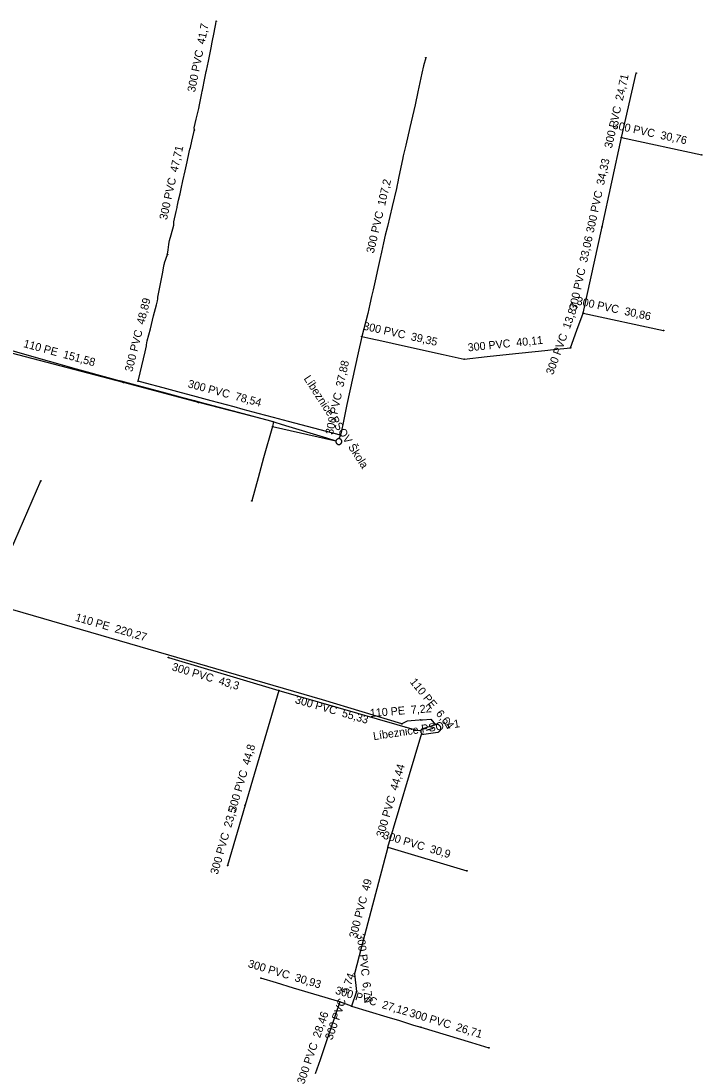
# Model space of a CAD drawing. Extents: x -736536 to -735428, y -1032997 to -1031649.
# Drawn here: x -735684.2 to -735428.6, y -1032358.4 to -1031967 of the extents above; entities that cross this region are included whole.
import ezdxf

# ---------------------------------------------------------------- set-up
doc = ezdxf.new("R2010")
doc.units = 0
for name, color, linetype in [('Vrstva 1', 7, 'Continuous'), ('Vrstva 20', 7, 'Continuous'), ('Vrstva 26', 7, 'Continuous'), ('Vrstva 29', 7, 'Continuous'), ('Vrstva 63', 7, 'Continuous')]:
    doc.layers.add(name, color=color, linetype=linetype)

# ---------------------------------------------------------------- blocks, each defined once
blk = doc.blocks.new('100')
at = {"layer": 'Vrstva 1'}
blk.add_circle((0, 0), 0.127, dxfattribs=at)

msp = doc.modelspace()

# ---------------------------------------------------------------- linework, layer by layer
at = {"layer": 'Vrstva 20'}
for p, q in [((-735458.86, -1032010.73), (-735453.32, -1031986.65)), ((-735466.16, -1032044.27), (-735458.86, -1032010.73)), ((-735458.86, -1032010.73), (-735428.79, -1032017.22)), ((-735473.28, -1032076.55), (-735466.16, -1032044.27)), ((-735473.28, -1032076.55), (-735443.12, -1032083.07)), ((-735645.66, -1032102.59), (-735715.244, -1032084.381)), ((-735617.54, -1032110.05), (-735645.66, -1032102.59)), ((-735589.45, -1032117.35), (-735617.54, -1032110.05)), ((-735589.45, -1032117.35), (-735589.74, -1032119.01)), ((-735589.74, -1032119.01), (-735565.962, -1032124.454)), ((-735564.26, -1032122.35), (-735564.87, -1032123.71)), ((-735698.803, -1032190.303), (-735676.675, -1032139.454)), ((-735628.82, -1032205.61), (-735587.37, -1032217.978)), ((-735587.37, -1032217.978), (-735600.075, -1032260.977)), ((-735600.075, -1032260.977), (-735606.6, -1032283.564)), ((-735546.475, -1032276.767), (-735516.898, -1032285.582)), ((-735559.05, -1032324.13), (-735558.24, -1032330.84)), ((-735558.24, -1032330.84), (-735560.13, -1032336.26)), ((-735560.13, -1032336.26), (-735564.49, -1032334.7))]:
    msp.add_line(p, q, dxfattribs=at)
for points in [[(-735619.095, -1032007.99), (-735619.03, -1032007.69), (-735619.18, -1032007.08), (-735618.392, -1032003.904), (-735617.51, -1032000.35), (-735617.39, -1031999.91), (-735617.127, -1031998.504), (-735616.299, -1031994.07), (-735616.18, -1031993.43), (-735616.09, -1031993.04), (-735615.191, -1031988.559), (-735614.67, -1031985.96), (-735614.52, -1031985.62), (-735613.807, -1031982.084), (-735612.813, -1031977.158), (-735612.378, -1031974.993), (-735611.67, -1031971.354), (-735611.42, -1031970.07), (-735611.05, -1031968.166), (-735610.86, -1031967.19)], [(-735532.28, -1031980.85), (-735533.13, -1031983.85), (-735533.735, -1031986.653), (-735535.246, -1031993.65), (-735536.298, -1031998.522), (-735538.256, -1032007.008), (-735539.784, -1032013.608), (-735540.726, -1032017.675), (-735541.03, -1032018.99), (-735542.368, -1032025.376), (-735542.914, -1032028.022), (-735543, -1032028.44), (-735543.325, -1032029.814), (-735544.917, -1032036.554), (-735546.686, -1032044.042), (-735547.47, -1032047.36), (-735548.108, -1032050.234), (-735548.876, -1032053.69), (-735549.485, -1032056.417), (-735550.248, -1032059.817), (-735551.28, -1032064.403), (-735552.049, -1032067.836), (-735552.583, -1032070.316), (-735553.22, -1032073.17), (-735554.05, -1032076.675), (-735556.31, -1032085.31)], [(-735629.165, -1032054.543), (-735629.159, -1032054.506), (-735628.907, -1032052.814), (-735628.614, -1032050.852), (-735628.49, -1032050.02), (-735628.44, -1032049.41), (-735627.817, -1032047.174), (-735626.821, -1032043.596), (-735626.73, -1032043.27), (-735626.83, -1032042.41), (-735625.93, -1032038.5), (-735625.589, -1032037.015), (-735625.5, -1032036.63), (-735625.44, -1032036.06), (-735625.019, -1032034.215), (-735624.469, -1032031.799), (-735624.055, -1032029.983), (-735623.399, -1032026.979), (-735622.559, -1032023.228), (-735621.818, -1032019.923), (-735620.987, -1032016.211), (-735620.74, -1032015.11), (-735620.58, -1032014.5), (-735620.021, -1032012.057), (-735619.303, -1032008.916), (-735619.16, -1032008.29), (-735619.095, -1032007.99)], [(-735640.14, -1032102.1), (-735639.387, -1032098.888), (-735637.564, -1032091.121), (-735637.02, -1032088.8), (-735637.09, -1032088.41), (-735636.737, -1032087.005), (-735635.587, -1032082.434), (-735634.369, -1032077.588), (-735633.332, -1032073.463), (-735632.951, -1032071.948), (-735632.75, -1032071.15), (-735632.76, -1032070.58), (-735632.269, -1032068.051), (-735630.939, -1032061.202), (-735630.622, -1032059.565), (-735630.38, -1032058.32), (-735630.32, -1032058.005), (-735630.26, -1032057.69), (-735629.17, -1032054.58), (-735629.165, -1032054.543)], [(-735478.02, -1032089.58), (-735475.62, -1032082.983), (-735473.28, -1032076.55)], [(-735711.93, -1032083.64), (-735710.215, -1032084.147), (-735706.827, -1032085.147), (-735703.84, -1032086.03), (-735701.86, -1032086.591), (-735696.429, -1032088.129), (-735687.14, -1032090.76), (-735673.546, -1032094.61), (-735670.44, -1032095.49), (-735663.396, -1032097.408), (-735648.81, -1032101.381), (-735646.72, -1032101.95), (-735642.593, -1032103.055), (-735629.88, -1032106.459), (-735624.464, -1032107.91), (-735619.062, -1032109.356), (-735616.92, -1032109.93), (-735602.71, -1032113.7), (-735590.5, -1032116.94), (-735584.952, -1032118.64), (-735569.541, -1032123.361), (-735566.41, -1032124.32), (-735565.957, -1032124.433)], [(-735556.31, -1032085.31), (-735557.667, -1032091.471), (-735561.93, -1032110.83), (-735563.196, -1032117.088), (-735564.042, -1032121.273), (-735564.26, -1032122.35)], [(-735556.31, -1032085.31), (-735552.942, -1032086.058), (-735548.826, -1032086.972), (-735541.067, -1032088.695), (-735525.707, -1032092.106), (-735517.9, -1032093.84)], [(-735517.9, -1032093.84), (-735509.211, -1032092.834), (-735500.966, -1032091.967), (-735487.583, -1032090.601), (-735484.342, -1032090.248), (-735478.02, -1032089.58)], [(-735564.26, -1032122.35), (-735569.543, -1032120.944), (-735583.791, -1032117.153), (-735589.462, -1032115.644), (-735595.094, -1032114.145), (-735600.75, -1032112.64), (-735604.144, -1032111.735), (-735612.776, -1032109.424), (-735619.63, -1032107.59), (-735623.875, -1032106.453), (-735630.726, -1032104.62), (-735637.394, -1032102.835), (-735640.14, -1032102.1)], [(-735589.74, -1032119.01), (-735593.12, -1032130.83), (-735595.161, -1032138.3), (-735597.53, -1032146.97)], [(-735541.28, -1032230.47), (-735571.062, -1032221.558), (-735694.194, -1032185.738), (-735696.415, -1032191.131), (-735716.431, -1032239.875), (-735718.846, -1032239.806)], [(-735587.37, -1032217.978), (-735535.76, -1032232.887), (-735534.549, -1032232.97), (-735534.151, -1032232.997)], [(-735534.316, -1032229.048), (-735534.797, -1032229.103), (-735539.26, -1032229.46), (-735541.28, -1032230.47)], [(-735534.316, -1032229.048), (-735533.52, -1032228.957), (-735530.441, -1032228.709), (-735528.7, -1032230.836)], [(-735546.475, -1032276.767), (-735534.149, -1032235.217), (-735533.799, -1032234.169)], [(-735529.544, -1032232.225), (-735529.624, -1032232.247), (-735531.755, -1032232.838), (-735532.134, -1032232.944)], [(-735546.475, -1032276.767), (-735556.378, -1032314.067), (-735559.05, -1032324.13)], [(-735564.49, -1032334.7), (-735581.866, -1032329.504), (-735588.265, -1032327.591), (-735594.12, -1032325.84)], [(-735564.49, -1032334.7), (-735569.907, -1032350.464), (-735571.96, -1032356.44), (-735573.74, -1032361.62)], [(-735560.13, -1032336.26), (-735546.868, -1032340.309), (-735542.172, -1032341.743), (-735536.85, -1032343.368), (-735534.19, -1032344.18)], [(-735534.19, -1032344.18), (-735515.14, -1032349.971), (-735508.63, -1032351.95)]]:
    msp.add_lwpolyline(points, dxfattribs=at)
at = {"layer": 'Vrstva 26'}
for points in [[(-735565.44, -1032123.747), (-735565.537, -1032123.81), (-735565.626, -1032123.883), (-735565.707, -1032123.964), (-735565.78, -1032124.053), (-735565.843, -1032124.15), (-735565.895, -1032124.253), (-735565.936, -1032124.36), (-735565.966, -1032124.471), (-735565.984, -1032124.585), (-735565.99, -1032124.7), (-735565.984, -1032124.815), (-735565.966, -1032124.929), (-735565.936, -1032125.04), (-735565.895, -1032125.147), (-735565.845, -1032125.245), (-735565.78, -1032125.347), (-735565.707, -1032125.436), (-735565.626, -1032125.517), (-735565.535, -1032125.591), (-735565.44, -1032125.653), (-735565.337, -1032125.705), (-735565.23, -1032125.746), (-735565.119, -1032125.776), (-735565.005, -1032125.794), (-735564.89, -1032125.8), (-735564.775, -1032125.794), (-735564.667, -1032125.777), (-735564.55, -1032125.746), (-735564.443, -1032125.705), (-735564.34, -1032125.653), (-735564.243, -1032125.59), (-735564.154, -1032125.517), (-735564.073, -1032125.436), (-735564, -1032125.347), (-735563.937, -1032125.25), (-735563.885, -1032125.147), (-735563.844, -1032125.04), (-735563.814, -1032124.929), (-735563.796, -1032124.815), (-735563.79, -1032124.7), (-735563.796, -1032124.585), (-735563.814, -1032124.471), (-735563.844, -1032124.36), (-735563.885, -1032124.253), (-735563.937, -1032124.15), (-735564, -1032124.053), (-735564.073, -1032123.964), (-735564.154, -1032123.883), (-735564.243, -1032123.81), (-735564.34, -1032123.747), (-735564.443, -1032123.695), (-735564.55, -1032123.654), (-735564.656, -1032123.626), (-735564.775, -1032123.606), (-735564.89, -1032123.6), (-735565.005, -1032123.606), (-735565.119, -1032123.624), (-735565.23, -1032123.654), (-735565.332, -1032123.693), (-735565.44, -1032123.747)], [(-735533.929, -1032234.049), (-735533.85, -1032234.128), (-735533.762, -1032234.199), (-735533.668, -1032234.26), (-735533.568, -1032234.311), (-735533.463, -1032234.351), (-735533.355, -1032234.38), (-735533.244, -1032234.398), (-735533.132, -1032234.403), (-735533.02, -1032234.398), (-735527.774, -1032233.603), (-735527.629, -1032233.565), (-735527.482, -1032233.509), (-735527.345, -1032233.439), (-735527.216, -1032233.355), (-735527.097, -1032233.259), (-735526.989, -1032233.15), (-735526.892, -1032233.031), (-735526.808, -1032232.902), (-735526.739, -1032232.765), (-735526.684, -1032232.622), (-735526.644, -1032232.474), (-735526.62, -1032232.322), (-735526.612, -1032232.169), (-735526.62, -1032232.015), (-735526.644, -1032231.864), (-735526.684, -1032231.715), (-735526.739, -1032231.572), (-735526.808, -1032231.435), (-735526.892, -1032231.307), (-735526.986, -1032231.191), (-735527.097, -1032231.079), (-735527.212, -1032230.986), (-735527.345, -1032230.898), (-735527.482, -1032230.829), (-735527.625, -1032230.774), (-735527.774, -1032230.734), (-735527.925, -1032230.71), (-735528.079, -1032230.702), (-735528.238, -1032230.711), (-735528.384, -1032230.734), (-735528.532, -1032230.774), (-735528.675, -1032230.829), (-735533.463, -1032232.311), (-735533.568, -1032232.351), (-735533.668, -1032232.402), (-735533.762, -1032232.463), (-735533.847, -1032232.532), (-735533.929, -1032232.613), (-735534, -1032232.701), (-735534.061, -1032232.795), (-735534.112, -1032232.895), (-735534.152, -1032233), (-735534.181, -1032233.108), (-735534.199, -1032233.219), (-735534.204, -1032233.331), (-735534.199, -1032233.443), (-735534.182, -1032233.55), (-735534.152, -1032233.662), (-735534.112, -1032233.767), (-735534.061, -1032233.867), (-735534, -1032233.961), (-735533.929, -1032234.049)]]:
    msp.add_lwpolyline(points, dxfattribs=at)

# ---------------------------------------------------------------- block references
at = {"layer": 'Vrstva 29'}
for p, xscale, yscale, rotation in [((-735610.86, -1031967.19), 0.999999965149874, 0.9999999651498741, -102.0000000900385), ((-735532.28, -1031980.85), 0.9999999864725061, 0.9999999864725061, 74.0000013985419), ((-735453.32, -1031986.65), 0.9999999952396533, 0.9999999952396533, 77.00000056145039), ((-735619.095, -1032007.99), 0.9999999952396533, 0.9999999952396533, -102.9999994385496), ((-735458.86, -1032010.73), 0.9999999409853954, 0.9999999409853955, -104.00000032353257), ((-735428.79, -1032017.22), 1.0028916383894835, 1.0028916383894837, -13.697207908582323), ((-735466.16, -1032044.27), 0.9999999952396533, 0.9999999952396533, -102.9999994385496), ((-735629.165, -1032054.543), 0.9999999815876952, 0.9999999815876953, 82.0000004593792), ((-735473.28, -1032076.55), 0.9999999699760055, 0.9999999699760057, -106.99999966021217), ((-735556.31, -1032085.31), 0.9999999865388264, 0.9999999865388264, -59.99999955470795), ((-735443.12, -1032083.07), 1.0028916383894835, 1.0028916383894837, -13.697207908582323), ((-735478.02, -1032089.58), 0.9999999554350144, 0.9999999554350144, -143.00000079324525), ((-735517.9, -1032093.84), 1.0002788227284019, 1.0002788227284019, 176.70930040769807), ((-735645.66, -1032102.59), 0.999999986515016, 0.9999999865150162, 164.99999987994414), ((-735640.14, -1032102.1), 0.9999999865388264, 0.9999999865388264, -59.99999955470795), ((-735617.54, -1032110.05), 0.999999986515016, 0.9999999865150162, 164.99999987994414), ((-735589.45, -1032117.35), 0.9999999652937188, 0.9999999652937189, -58.00000261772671), ((-735589.74, -1032119.01), 0.9999999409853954, 0.9999999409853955, -104.00000032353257), ((-735564.26, -1032122.35), 0.9999999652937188, 0.9999999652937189, 31.9999973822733), ((-735676.675, -1032139.454), 0.999999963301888, 0.9999999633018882, 69.00000101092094), ((-735597.53, -1032146.97), 0.9999999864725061, 0.9999999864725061, -105.99999860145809), ((-735628.82, -1032205.61), 1.0335064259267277, 1.033506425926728, -23.04128150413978), ((-735587.37, -1032217.978), 1.0365458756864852, 1.0365458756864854, 158.02850914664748), ((-735541.28, -1032230.47), 0.9999999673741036, 0.9999999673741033, -176.00000004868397), ((-735534.316, -1032229.048), 1.0011216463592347, 1.0011216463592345, -173.41738977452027), ((-735600.075, -1032260.977), 0.9999999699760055, 0.9999999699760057, -106.99999966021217), ((-735546.475, -1032276.767), 0.999999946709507, 0.999999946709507, -62.999999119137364), ((-735606.6, -1032283.564), 0.9999999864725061, 0.9999999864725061, 74.0000013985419), ((-735516.898, -1032285.582), 1.035124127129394, 1.0351241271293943, 157.49634583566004), ((-735559.05, -1032324.13), 0.9999999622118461, 0.999999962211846, -94.99999985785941), ((-735594.12, -1032325.84), 1.035124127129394, 1.0351241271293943, 157.49634583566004), ((-735558.24, -1032330.84), 1.0011216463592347, 1.0011216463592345, 83.41738977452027), ((-735564.49, -1032334.7), 1.0316957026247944, 1.0316957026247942, -23.584588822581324), ((-735560.13, -1032336.26), 1.0138864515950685, 1.0138864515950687, 27.5653151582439), ((-735534.19, -1032344.18), 1.0335064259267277, 1.033506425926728, -23.04128150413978), ((-735508.63, -1032351.95), 1.0335064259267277, 1.033506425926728, -23.04128150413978)]:
    msp.add_blockref('100', p, dxfattribs=dict(at, xscale=xscale, yscale=yscale, rotation=rotation))

# ---------------------------------------------------------------- texts
at = {"layer": 'Vrstva 63'}
for s, rotation, p in [('300 PVC  41,7', 78.59, (-735618.851, -1031993.932)), ('300 PVC  24,71', 77.04, (-735462.504, -1032014.967)), ('300 PVC  30,76', 347.82, (-735462.372, -1032007.358)), ('300 PVC  47,71', 77.37, (-735629.385, -1032041.801)), ('300 PVC  34,33', 77.72, (-735469.341, -1032046.659)), ('300 PVC  107,2', 76.71, (-735551.787, -1032054.333)), ('300 PVC  33,06', 77.56, (-735475.744, -1032075.649)), ('300 PVC  48,89', 75.89, (-735642.377, -1032098.781)), ('300 PVC  30,86', 347.8, (-735475.873, -1032073.328)), ('300 PVC  13,87', 70.01, (-735484.541, -1032099.902)), ('300 PVC  39,35', 347.48, (-735555.945, -1032082.728)), ('110 PE  151,58', 344.77, (-735683.411, -1032089.264)), ('300 PVC  40,11', 5.83, (-735516.388, -1032090.927)), ('300 PVC  37,88', 77.58, (-735567.126, -1032122.337)), ('300 PVC  78,54', 345.02, (-735621.746, -1032104.333)), ('Líbeznice PSOV Škola', 303, (-735578.199, -1032101.087)), ('110 PE  220,27', 343.78, (-735663.966, -1032191.823)), ('300 PVC  43,3', 343.39, (-735627.746, -1032210.371)), ('110 PE  6,64', 309.29, (-735538.42, -1032214.851)), ('300 PVC  55,33', 343.89, (-735581.528, -1032222.67)), ('110 PE  7,22', 4.57, (-735553.121, -1032227.959)), ('Líbeznice PSOV 1', 8.61, (-735551.803, -1032236.634)), ('300 PVC  44,8', 73.54, (-735603.591, -1032263.702)), ('300 PVC  44,44', 73.48, (-735548.139, -1032273.239)), ('300 PVC  23,5', 73.89, (-735610.349, -1032287.177)), ('300 PVC  30,9', 343.4, (-735548.524, -1032273.442)), ('300 PVC  49', 75.13, (-735558.262, -1032311.032)), ('300 PVC  6,76', 276.88, (-735558.225, -1032309.256)), ('300 PVC  30,93', 343.35, (-735599.206, -1032321.604)), ('300 PVC  5,74', 70.78, (-735567.393, -1032349.198)), ('300 PVC  27,12', 343.02, (-735566.446, -1032331.612)), ('300 PVC  28,46', 71.04, (-735577.904, -1032365.739)), ('300 PVC  26,71', 343.09, (-735538.692, -1032340.093))]:
    msp.add_text(s, height=2.99999, rotation=rotation, dxfattribs=at).set_placement(p)

doc.saveas('drawing.dxf')
